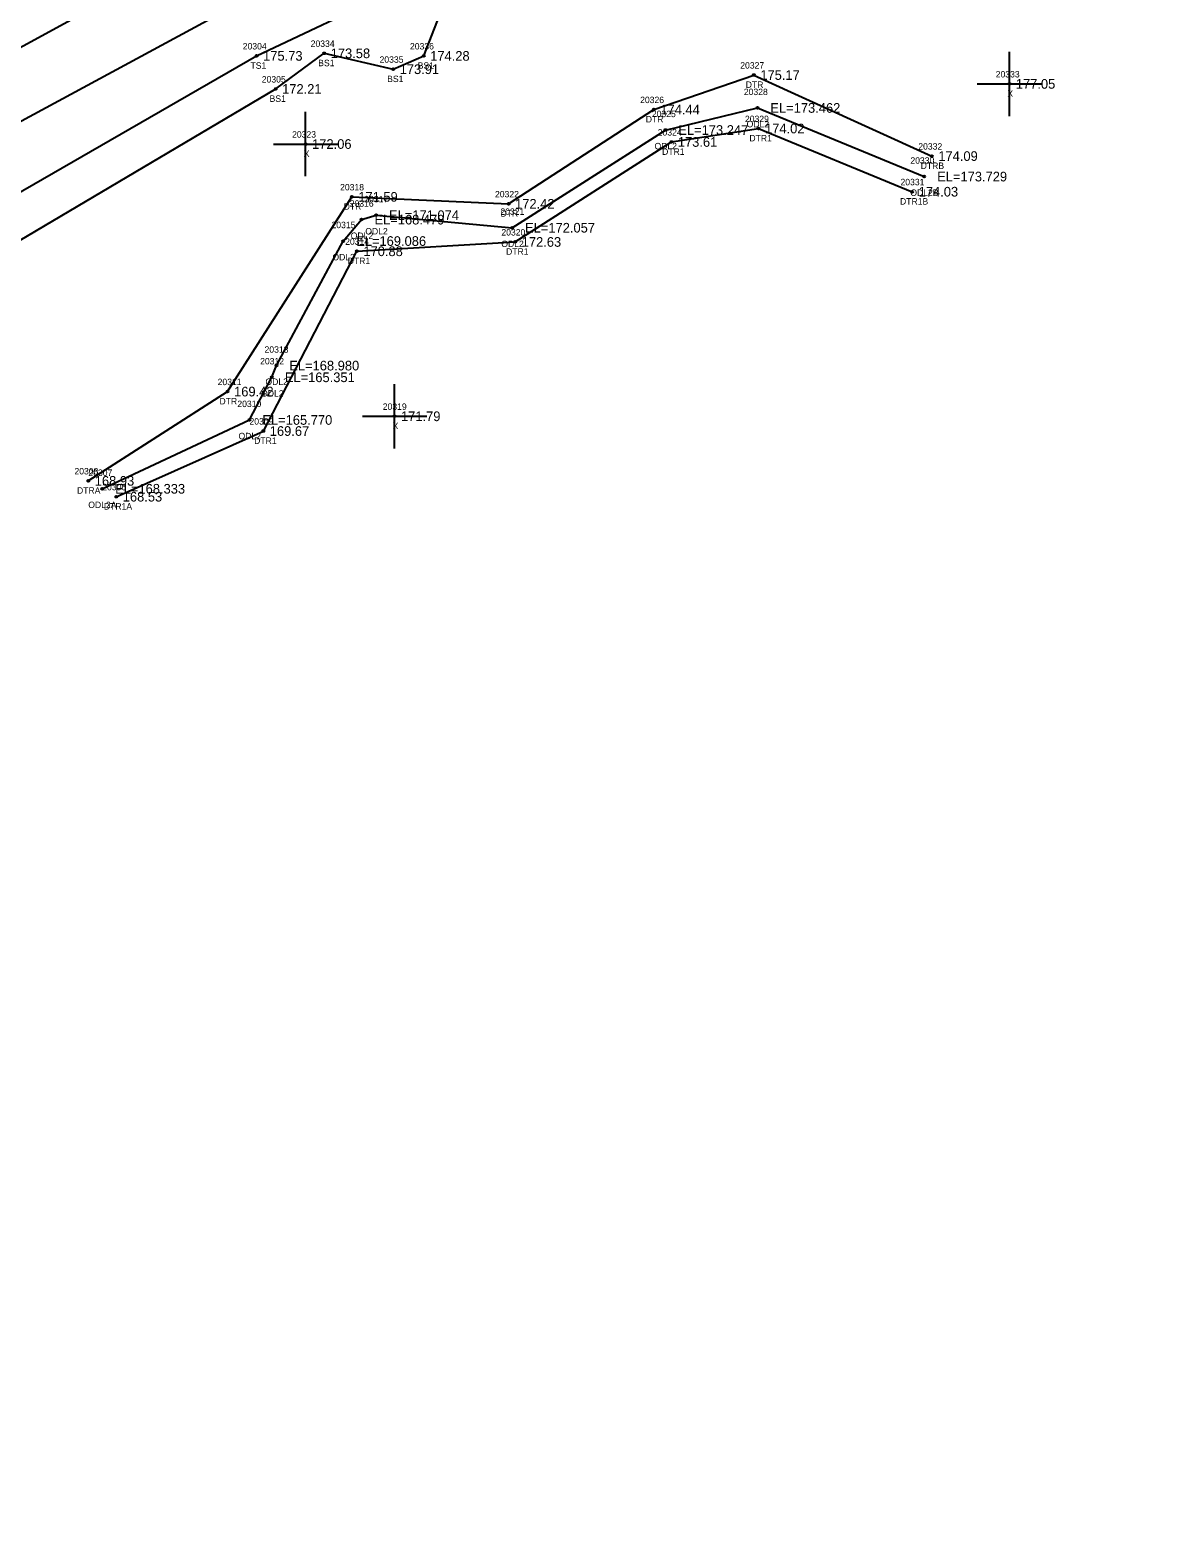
# Model space of a CAD drawing. Extents: x 2279528 to 2280976, y 1061373 to 1062235.
# Drawn here: x 2280628.7 to 2280803.4, y 1061781 to 1062015.3 of the extents above; entities that cross this region are included whole.
import ezdxf

# ---------------------------------------------------------------- set-up
doc = ezdxf.new("R2010")
doc.units = 0
for name, color, linetype in [('RD_DTM_BkLn1', 7, 'Continuous'), ('RD_DTM_BkLn2', 7, 'Continuous'), ('RD_DTM_BkLn_txCode', 7, 'Continuous'), ('RD_EX_H2O', 7, 'Continuous'), ('RD_EX_H2O_txCode', 7, 'Continuous'), ('RD_EX_Misc', 7, 'Continuous'), ('RD_EX_Misc_txCode', 7, 'Continuous'), ('RD_EX_Road', 7, 'Continuous'), ('RD_EX_TX_H2O_ELEV', 7, 'Continuous'), ('RD_EX_TX_Misc_ELEV', 7, 'Continuous'), ('RD_SMD_Locator', 7, 'Continuous')]:
    doc.layers.add(name, color=color, linetype=linetype)

msp = doc.modelspace()

# ---------------------------------------------------------------- linework, layer by layer
at = {"layer": 'RD_DTM_BkLn1'}
msp.add_lwpolyline([(2279559.79, 1061433.13), (2279641.23, 1061477.49), (2279727.93, 1061524.84), (2279814.76, 1061571.75), (2279901.26, 1061618.64), (2279982.8, 1061662.56), (2280064.7, 1061706.86), (2280148.08, 1061751.86), (2280234.22, 1061798.46), (2280310.96, 1061840.01), (2280397.69, 1061887.57), (2280487.27, 1061936.5), (2280573.03, 1061983.12), (2280654.64, 1062027.66), (2280741.28, 1062074.45), (2280833.39, 1062123.87), (2280892.52, 1062155.9), (2280939.46, 1062181.85)], dxfattribs=at)
at = {"layer": 'RD_DTM_BkLn2'}
for points in [[(2280272.88, 1061795.9), (2280297.58, 1061791.78), (2280309.49, 1061810.68), (2280320.64, 1061820.76), (2280406.65, 1061872.9), (2280496.79, 1061919.98), (2280582.43, 1061964.41), (2280663.95, 1062011.32), (2280685.25, 1062021.45), (2280750.74, 1062056.04), (2280766.13, 1062062.47), (2280799.22, 1062079.83)], [(2280270.02, 1061790.74), (2280279.94, 1061788.98), (2280298.7, 1061789.36), (2280312.74, 1061804.74), (2280323.13, 1061815.81), (2280411.42, 1061866.03), (2280499.93, 1061915.08), (2280584.56, 1061957.49), (2280666.91, 1062006.18), (2280674.46, 1062011.72), (2280685.18, 1062009.25), (2280689.93, 1062011.32), (2280693.25, 1062019.83), (2280753.26, 1062052.49), (2280766.38, 1062057.83), (2280800.29, 1062072.08)]]:
    msp.add_lwpolyline(points, dxfattribs=at)
at = {"layer": 'RD_EX_H2O'}
for points in [[(2280637.78, 1061945.26), (2280659.44, 1061959.14), (2280678.75, 1061989.41), (2280703.13, 1061988.33), (2280725.72, 1062002.98), (2280741.26, 1062008.35), (2280768.93, 1061995.75)], [(2280639.95, 1061944.03), (2280662.83, 1061954.73), (2280666.33, 1061961.36), (2280667.02, 1061963.18), (2280677.42, 1061982.54), (2280680.27, 1061985.87), (2280682.53, 1061986.56), (2280703.68, 1061984.61), (2280727.51, 1061999.8), (2280741.82, 1062003.23), (2280767.75, 1061992.56)], [(2280642.13, 1061942.8), (2280664.99, 1061953.01), (2280679.54, 1061980.95), (2280704.16, 1061982.4), (2280728.43, 1061997.94), (2280741.99, 1062000.03), (2280765.88, 1061990.21)]]:
    msp.add_lwpolyline(points, dxfattribs=at)
at = {"layer": 'RD_EX_Misc'}
for p, q in [((2280780.98, 1062001.97), (2280780.98, 1062011.97)), ((2280775.98, 1062006.97), (2280785.98, 1062006.97)), ((2280671.57, 1061992.62), (2280671.57, 1062002.62)), ((2280666.57, 1061997.62), (2280676.57, 1061997.62)), ((2280685.39, 1061950.3), (2280685.39, 1061960.3)), ((2280680.39, 1061955.3), (2280690.39, 1061955.3))]:
    msp.add_line(p, q, dxfattribs=at)
at = {"layer": 'RD_EX_Road'}
msp.add_lwpolyline([(2280403.05, 1061879.04), (2280492, 1061927.92), (2280577.25, 1061974.17), (2280660.08, 1062018.91), (2280745.99, 1062065.19), (2280838.21, 1062115.39), (2280896.66, 1062146.92), (2280943.94, 1062172.8)], dxfattribs=at)
at = {"layer": 'RD_SMD_Locator'}
for centre in [(2280663.95, 1062011.32), (2280674.46, 1062011.72), (2280689.93, 1062011.32), (2280685.18, 1062009.25), (2280741.26, 1062008.35), (2280666.91, 1062006.18), (2280780.98, 1062006.97), (2280725.72, 1062002.98), (2280741.82, 1062003.23), (2280727.51, 1061999.8), (2280741.99, 1062000.03), (2280671.57, 1061997.62), (2280728.43, 1061997.94), (2280768.93, 1061995.75), (2280767.75, 1061992.56), (2280765.88, 1061990.21), (2280678.75, 1061989.41), (2280703.13, 1061988.33), (2280680.27, 1061985.87), (2280682.53, 1061986.56), (2280677.42, 1061982.54), (2280703.68, 1061984.61), (2280679.54, 1061980.95), (2280704.16, 1061982.4), (2280666.33, 1061961.36), (2280667.02, 1061963.18), (2280659.44, 1061959.14), (2280662.83, 1061954.73), (2280685.39, 1061955.3), (2280664.99, 1061953.01), (2280637.78, 1061945.26), (2280639.95, 1061944.03), (2280642.13, 1061942.8)]:
    msp.add_circle(centre, 0.15, dxfattribs=at)

# ---------------------------------------------------------------- texts
at = {"layer": 'RD_DTM_BkLn_txCode'}
for s, p in [('20304', (2280661.79, 1062012.32)), ('20334', (2280672.35, 1062012.72)), ('20336', (2280687.79, 1062012.32)), ('BS1', (2280673.52, 1062009.72)), ('20335', (2280683.06, 1062010.25)), ('TS1', (2280662.99, 1062009.32)), ('BS1', (2280688.99, 1062009.32)), ('20305', (2280664.75, 1062007.18)), ('BS1', (2280684.24, 1062007.25)), ('BS1', (2280665.96, 1062004.18))]:
    msp.add_text(s, height=1, dxfattribs=at).set_placement(p)
at = {"layer": 'RD_EX_H2O_txCode'}
for s, p in [('20327', (2280739.14, 1062009.35)), ('20328', (2280739.7, 1062005.23)), ('DTR', (2280739.99, 1062006.35)), ('20326', (2280723.57, 1062003.98)), ('DTR', (2280724.45, 1062000.98)), ('20325', (2280725.39, 1062001.8)), ('20329', (2280739.87, 1062001.03)), ('20324', (2280726.31, 1061998.94)), ('ODL2', (2280740.13, 1062000.23)), ('DTR1', (2280740.56, 1061998.03)), ('ODL2', (2280725.81, 1061996.8)), ('DTR1', (2280726.99, 1061995.94)), ('20332', (2280766.82, 1061996.75)), ('20330', (2280765.59, 1061994.56)), ('DTRB', (2280767.19, 1061993.75)), ('20331', (2280764.05, 1061991.21)), ('20318', (2280676.92, 1061990.41)), ('20322', (2280701.01, 1061989.33)), ('ODL2B', (2280765.58, 1061989.56)), ('DTR', (2280677.48, 1061987.41)), ('20316', (2280678.42, 1061987.87)), ('20317', (2280680.69, 1061988.56)), ('20321', (2280701.85, 1061986.61)), ('DTR', (2280701.86, 1061986.33)), ('DTR1B', (2280763.98, 1061988.21)), ('20315', (2280675.59, 1061984.54)), ('20314', (2280677.71, 1061981.95)), ('ODL2', (2280678.58, 1061982.87)), ('ODL2', (2280680.84, 1061983.56)), ('ODL2', (2280701.99, 1061981.61)), ('20320', (2280702, 1061983.4)), ('ODL2', (2280675.73, 1061979.54)), ('DTR1', (2280702.73, 1061980.4)), ('DTR1', (2280678.11, 1061978.95)), ('20313', (2280665.18, 1061965.18)), ('20312', (2280664.49, 1061963.36)), ('20311', (2280657.88, 1061960.14)), ('ODL2', (2280664.64, 1061958.36)), ('ODL2', (2280665.32, 1061960.18)), ('DTR', (2280658.17, 1061957.14)), ('20310', (2280660.95, 1061956.73)), ('20309', (2280662.83, 1061954.01)), ('ODL2', (2280661.13, 1061951.73)), ('DTR1', (2280663.56, 1061951.01)), ('20308', (2280635.62, 1061946.26)), ('20307', (2280637.79, 1061946.03)), ('DTRA', (2280636.02, 1061943.26)), ('20306', (2280639.94, 1061943.8)), ('ODL2A', (2280637.77, 1061941.03)), ('DTR1A', (2280640.2, 1061940.8))]:
    msp.add_text(s, height=1, dxfattribs=at).set_placement(p)
at = {"layer": 'RD_EX_Misc_txCode'}
for s, p in [('20333', (2280778.86, 1062007.97)), ('X', (2280780.67, 1062004.97)), ('20323', (2280669.46, 1061998.62)), ('X', (2280671.26, 1061995.62)), ('20319', (2280683.56, 1061956.3)), ('X', (2280685.08, 1061953.3))]:
    msp.add_text(s, height=1, dxfattribs=at).set_placement(p)
at = {"layer": 'RD_EX_TX_H2O_ELEV'}
for s, p in [('175.17', (2280742.26, 1062007.6)), ('174.44', (2280726.72, 1062002.23)), ('EL=173.462', (2280743.82, 1062002.48)), ('EL=173.247', (2280729.51, 1061999.05)), ('174.02', (2280742.99, 1061999.28)), ('173.61', (2280729.43, 1061997.19)), ('174.09', (2280769.93, 1061995)), ('EL=173.729', (2280769.75, 1061991.81)), ('171.59', (2280679.75, 1061988.66)), ('174.03', (2280766.88, 1061989.46)), ('EL=171.074', (2280684.53, 1061985.81)), ('172.42', (2280704.13, 1061987.58)), ('EL=168.479', (2280682.27, 1061985.12)), ('EL=172.057', (2280705.68, 1061983.86)), ('EL=169.086', (2280679.42, 1061981.79)), ('172.63', (2280705.16, 1061981.65)), ('170.88', (2280680.54, 1061980.2)), ('EL=168.980', (2280669.02, 1061962.43)), ('EL=165.351', (2280668.33, 1061960.61)), ('169.42', (2280660.44, 1061958.39)), ('EL=165.770', (2280664.83, 1061953.98)), ('169.67', (2280665.99, 1061952.26)), ('168.93', (2280638.78, 1061944.51)), ('EL=168.333', (2280641.95, 1061943.28)), ('168.53', (2280643.13, 1061942.05))]:
    msp.add_text(s, height=1.5, dxfattribs=at).set_placement(p)
at = {"layer": 'RD_EX_TX_Misc_ELEV'}
for s, p in [('175.73', (2280664.95, 1062010.57)), ('173.58', (2280675.46, 1062010.97)), ('174.28', (2280690.93, 1062010.57)), ('173.91', (2280686.18, 1062008.5)), ('172.21', (2280667.91, 1062005.43)), ('177.05', (2280781.98, 1062006.22)), ('172.06', (2280672.57, 1061996.87)), ('171.79', (2280686.39, 1061954.55))]:
    msp.add_text(s, height=1.5, dxfattribs=at).set_placement(p)

doc.saveas('drawing.dxf')
